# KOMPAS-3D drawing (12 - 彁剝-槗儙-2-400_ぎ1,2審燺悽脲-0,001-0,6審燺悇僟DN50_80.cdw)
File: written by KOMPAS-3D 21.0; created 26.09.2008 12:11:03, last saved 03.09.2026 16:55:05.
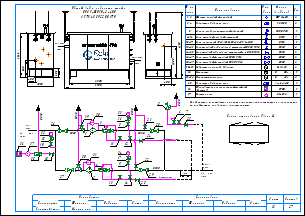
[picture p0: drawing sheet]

Sheets 1-2: A3, landscape

Document properties: Наименование: Макро:21; Автор: RaskoAdmin; Форматы листов документа: 2xA3; Полное имя файла: \\UR38nt01\Departments\КТО\КБ ПУРДГ\Заявки\Прайс-лист на типовые шкафы ГРПШ\ПРДГ_стандарт_20_03_2026\ПРДГ с РДГ(Н, В)\ПРДГ-ШУГО-2-400_до1,2МПа_Рвых-0,001-0,6МПа_РДГ_DN50_80.cdw

Title block, sheet 1: Наименование: Пункт учета газа / ПУГ-Ш-400-Р / ЛГТИ.485922.001ТУ; designation: ЛГТИ.03.4411141; sheet number: 1; Количество листов документа: 2; organisation: ООО "ЭЛЬСТЕР Газэлектроника"; Форматы листов документа: A3; stored path: C:\Рабочие документы\Компас\ПУГ\Схема.cdw; Разработал: Устинов; Проверил: Кошкин; Утвердил: Кошкин
Title block, sheet 2: sheet number: 2; stored path: D:\Рабочие документы\Заявки\ПУРДГ\ПУРДГ-ШУЭО-2-100-Р 4411220.cdw; designation, second copy: ЛГТИ.03.4411141-

Views: Вид 1, Вид 2
Referenced files: wcvoit.frw
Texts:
  Normal
  Общий вид и габариты шкафа
  ПРДГ-ШУГО-2-400
  Вход
  газа
  PDI
  Выход
  Р=     кПа
  DN80
  DN50
  DN20
  Импульс DN20
  ≥5DN
  HYSWLongFangSong
  Р=       МПа
  № на
  схеме
  Усл.
  обозн.
  Марка
  (модель)
  Кол.
  Фильтр газовый фланцевый
  ФГ 16-50
  Регулятор давления газа
  РДГ-50
  Клапан предохранительный сбросной
  КПС DN20
  Кран шаровой газовый латунный
  DN15
  Кран кнопочный VE-РАСКО-НЗ-1,6-G1/2-М20
  Кран шаровой "под приварку" штуцерный DN20 PN16
  Кран шаровой "под приварку" штуцерный п/п DN20 PN16
  Кран шаровой фланцевый DN50 PN16
  Кран шаровой фланцевый DN80 PN16
  Индикатор перепада давления
  Delta 15
  Манометр
  Манометр-напоромер
  0...     МПа
  0...     кПа
  Обогреватель газогорелочный шкафной
  (Эльтон")
  Счетчик газа
  Venio-A-15
  ОГШН
  BK-G1,6
  Схема открывания дверей
  Предприятие изготовитель может заменять комплектующие на аналогичные,
  не ухудшающие заявленных характеристик.
  Вход газа
  Выход газа
  logo-rasko-ge(1).png
  Должность
  Конструктор
  Фамилия
  Подпись
  Дата
  Согласовано
  Максимкин
  Лист
  Листов
  POLYLINE_STYLE_0.18_RGB_0_0_0
  POLYLINE_STYLE_0.50_RGB_0_0_0
  POLYLINE_STYLE_0.34_RGB_0_0_0
  PHANTOM_RGB_0_0_0_SC_1_THICK_0.18
  K5LT_THIN_RGB_0_0_0_THICK_0.18
  K5LT32769_RGB_0_0_0_THICK_0.18
  K5LT12_RGB_0_0_0_SC_1_THICK_0.18
  K5LT_DASHED_RGB_0_0_0_SC_1_THICK_0.18
  ACISOTGL_RGB_0_0_0_SC_0.8_THICK_0.25
  CONTINUOUS_RGB_0_127_31_THICK_0.3
  CONTINUOUS_RGB_0_0_255_THICK_0.35
  CONTINUOUS_RGB_255_0_0_THICK_0.35
  POLYLINE_STYLE_0.25_RGB_0_0_0
  CONTINUOUS_RGB_0_0_0_THICK_0.5
  POLYLINE_STYLE_0.35_RGB_0_0_255
  CONTINUOUS_RGB_0_0_0_THICK_0.4
  CONTINUOUS_RGB_0_0_0_THICK_0.35
  Без оформления
Dimensions and other numbers on the sheet: 1; 2; 3; 4; 5; 10; 27; 28; 29; 23; 8; 12; 19; 20; 21; 22; 25; 24; 30; 31; 15; 16; 32; 26; 6; 7; 11; 14; 13; 33; 9; 17; 34; 18; 35; 36; 37; 1, 2; 3, 4; 6-14; 15-17; 18-23; 24-25; 26-27; 28-29; 30-31; 33-34; 400; 1050; 500; 305; 2800; 1565; 3100; 1000; 4130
